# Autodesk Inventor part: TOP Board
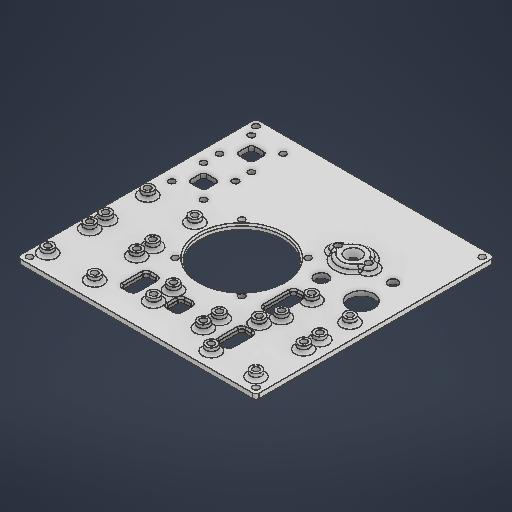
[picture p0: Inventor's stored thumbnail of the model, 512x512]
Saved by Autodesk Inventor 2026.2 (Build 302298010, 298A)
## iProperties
Created: 2026-05
Part Number: TOP Board
Material: 일반
Document SubType Name: Modeling
Designer: work
Density: 1 g/cm^3
Appearance: 기본값
Author: work
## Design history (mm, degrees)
sketch "스케치1"
  geometry: L1 (0, 0)-(150, 0); L2 (150, 0)-(150, -150); L3 (150, -150)-(0, -150); L4 (0, -150)-(0, 0); L5 (146, -4)-(4, -4); L6 (4, -4)-(4, -146); L7 (4, -146)-(146, -146); L8 (146, -146)-(146, -4); L9 (10, -10)-(38, -10); L10 (38, -10)-(38, -40); L11 (38, -40)-(10, -40); L12 (10, -40)-(10, -10); L13 (34, -17)-(42, -17); L14 (42, -17)-(42, -33); L15 (42, -33)-(34, -33); L16 (34, -33)-(34, -17); L17 (34, -17)-(42, -33); L18 (42, -17)-(34, -33); L19 (10, -50)-(34, -50); L20 (34, -50)-(34, -69); L21 (34, -69)-(10, -69); L22 (10, -69)-(10, -50); L23 (10, -50)-(34, -69); L24 (34, -50)-(10, -69); L25 (53, -20)-(53, -30); L26 (38, -25)-(53, -25); L27 (68.5, -17.5)-(49.5, -17.5); L28 (49.5, -17.5)-(49.5, -32.5); L29 (49.5, -32.5)-(68.5, -32.5); L30 (68.5, -32.5)-(68.5, -17.5); L31 (68.5, -17.5)-(49.5, -32.5); L32 (49.5, -17.5)-(68.5, -32.5); L33 (53, -25)-(59, -25); L34 (43, -84)-(18, -84); L35 (18, -104)-(18, -69); L36 (58.14, -49.14)-(99.86, -49.14); L37 (99.86, -49.14)-(99.86, -90.86); L38 (99.86, -90.86)-(58.14, -90.86); L39 (58.14, -90.86)-(58.14, -49.14); L40 (58.14, -49.14)-(99.86, -90.86); L41 (99.86, -49.14)-(58.14, -90.86); L42 (38, -49.5)-(46, -49.5); L43 (46, -49.5)-(46, -69.5); L44 (46, -69.5)-(38, -69.5); L45 (38, -69.5)-(38, -49.5); L46 (38, -49.5)-(46, -69.5); L47 (46, -49.5)-(38, -69.5); L48 (22, -59.5)-(42, -59.5); L49 (69, -20)-(77, -20); L50 (77, -20)-(77, -30); L51 (77, -30)-(69, -30); L52 (69, -30)-(69, -20); L53 (69, -20)-(77, -30); L54 (77, -20)-(69, -30); L55 (59, -25)-(73, -25); L56 (83, -18.75)-(83, -31.25); L57 (94, -17)-(102, -17); L58 (102, -17)-(102, -33); L59 (102, -33)-(94, -33); L60 (94, -33)-(94, -17); L61 (94, -17)-(102, -33); L62 (102, -17)-(94, -33); L63 (83, -25)-(98, -25); L64 (113, -11.8)-(142.5, -11.8)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; C1 r 2 at (146, -4); C2 r 2 at (4, -4); C3 r 2 at (4, -146); C4 r 2 at (146, -146); C5 r 2 at (10, -10); C6 r 2 at (38, -10); C7 r 2 at (38, -40); C8 r 2 at (10, -40); C9 r 2 at (10, -50); C10 r 2 at (34, -50); C11 r 2 at (34, -69); C12 r 2 at (10, -69); C13 r 1.6 at (53, -20); C14 r 1.6 at (53, -30); C15 r 8 at (18, -84); C16 r 4.15 at (43, -84); C17 r 3 at (18, -104); C18 r 26 at (79, -70); C19 r 2 at (99.86, -49.14); C20 r 2 at (58.14, -49.14); C21 r 2 at (58.14, -90.86); C22 r 2 at (99.86, -90.86); C23 r 2 at (83, -18.75); C24 r 2 at (83, -31.25); C25 r 2 at (113, -11.8); C26 r 2 at (113, -38.2); C27 r 2 at (142.5, -38.2); C28 r 2 at (142.5, -11.8); C29 r 2 at (113, -74.6); C30 r 2 at (113, -48.2); C31 r 2 at (142.5, -48.2); C32 r 2 at (142.5, -74.6); C33 r 7.6 at (43, -104); C34 r 2 at (33.4, -104); C35 r 2 at (52.6, -104); C36 r 2 at (43, -104); C37 r 2 at (142.5, -89.6); C38 r 2 at (122.5, -89.6); C39 r 2 at (122.5, -109.6); C40 r 2 at (142.5, -109.6); C41 r 2 at (122.5, -119.6); C42 r 2 at (142.5, -119.6); C43 r 2 at (142.5, -139.6); C44 r 2 at (122.5, -139.6); 3 further points
  constraints: 220 end point, 44 centre point, 37 coincident, 34 parallel, 31 midpoint, 23 perpendicular, 22 horizontal, 6 collinear, 3 point on line, 3 vertical, 2 tangent
  dimensions: "d0" = 150 distance of L2.end L3.end; "d1" = 150 distance of L1.end L2.end; "d2" = 4 diameter of C1; "d3" = 4 diameter of C2; "d4" = 4 diameter of C3; "d5" = 4 diameter of C4; "d6" = 4 distance between parallel lines of L1 L5; "d7" = 4 distance between parallel lines of L4 L6; "d8" = 4 distance between parallel lines of L2 L8; "d9" = 4 distance between parallel lines of L3 L7; "d10" = 28 distance of L10.end L11.end; "d11" = 30 distance of L9.end L10.end; "d12" = 4 diameter of C5; "d13" = 4 diameter of C6; "d14" = 4 diameter of C7; "d15" = 4 diameter of C8; "d16" = 8 distance of L14.end L15.end; "d17" = 16 distance of L13.end L14.end; "d18" = 10 distance between parallel lines of L1 L9; "d19" = 10 distance between parallel lines of L4 L12; "d20" = 24 distance of L20.end L21.end; "d21" = 19 distance of L19.end L20.end; "d22" = 10 distance between parallel lines of L11 L19; "d23" = 4 diameter of C9; "d24" = 4 diameter of C10; "d25" = 4 diameter of C11; "d26" = 4 diameter of C12; "d27" = 10 distance of L25.start L25.end; "d28" = 3.2 diameter of C13; "d29" = 3.2 diameter of C14; "d30" = 15 distance of L26.start L26.end; "d31" = 19 distance of L29.end L28.end; "d32" = 15 distance of L28.end L27.end; "d33" = 6 distance of L26.end L33.end; "d34" = 16 diameter of C15; "d35" = 8 distance from line of L22 L34.end; "d36" = 15 distance from line of L21 L34.end; "d37" = 8.3 diameter of C16; "d38" = 25 distance of L34.start L34.end; "d39" = 6 diameter of C17; "d40" = 20 distance from line of L34 L35.start; "d42" = 52 diameter of C18; "d43" = 59 distance of L36.end L38.end; "d44" = 4 diameter of C19; "d45" = 4 diameter of C20; "d46" = 4 diameter of C21; "d47" = 4 diameter of C22; "d48" = 45 distance from line of L20 C18.centre; "d49" = 70 distance from line of L1 C18.centre; "d50" = 8 distance of L43.end L44.end; "d51" = 20 distance of L42.end L43.end; "d52" = 20 distance of L48.start L48.end; "d53" = 8 distance of L50.end L51.end; "d54" = 10 distance of L49.end L50.end; "d55" = 20 distance of L26.end L55.end; "d56" = 12.5 distance of L56.start L56.end; "d57" = 4 diameter of C23; "d58" = 4 diameter of C24; "d61" = 8 distance of L58.end L59.end; "d62" = 16 distance of L57.end L58.end; "d63" = 15 distance of L63.start L63.end; "d64" = 10 distance of L55.end L63.start; "d65" = 26.4 distance of L64.end L65.end; "d66" = 29.5 distance of L65.end L66.end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
extrude "돌출1" new body sketch "스케치1" distance "d100" = 3; taper "d101" = 0 deg
sketch "스케치2"
  geometry: L1 (0, 150)-(-150, 150) reference; L2 (-150, 150)-(-150, 0) reference; L3 (-150, 0)-(0, 0) reference; L4 (0, 0)-(0, 150) reference; L5 (-94, 17)-(-102, 17) reference; L6 (-102, 17)-(-102, 33) reference; L7 (-102, 33)-(-94, 33) reference; L8 (-94, 33)-(-94, 17) reference; L9 (-69, 20)-(-77, 20) reference; L10 (-77, 20)-(-77, 30) reference; L11 (-77, 30)-(-69, 30) reference; L12 (-69, 30)-(-69, 20) reference; L13 (-38, 49.5)-(-46, 49.5) reference; L14 (-46, 49.5)-(-46, 69.5) reference; L15 (-46, 69.5)-(-38, 69.5) reference; L16 (-38, 69.5)-(-38, 49.5) reference; L17 (-34, 17)-(-42, 17) reference; L18 (-42, 17)-(-42, 33) reference; L19 (-42, 33)-(-34, 33) reference; L20 (-34, 33)-(-34, 17) reference; C1 r 2 at (-122.5, 139.6) reference; C2 r 2 at (-142.5, 119.6) reference; C3 r 2 at (-142.5, 109.6) reference; C4 r 2 at (-122.5, 89.6) reference; C5 r 2 at (-43, 104) reference; C6 r 2 at (-33.4, 104) reference; C7 r 2 at (-142.5, 48.2) reference; C8 r 2 at (-113, 74.6) reference; C9 r 2 at (-142.5, 38.2) reference; C10 r 2 at (-113, 11.8) reference; C11 r 2 at (-83, 18.75) reference; C12 r 4.15 at (-43, 84) reference; C13 r 1.6 at (-53, 30) reference; C14 r 2 at (-10, 69) reference; C15 r 2 at (-34, 50) reference; C16 r 2 at (-10, 40) reference; C17 r 2 at (-38, 40) reference; C18 r 2 at (-38, 10) reference; C19 r 2 at (-10, 10) reference; C20 r 2 at (-146, 146) reference; C21 r 2 at (-4, 146) reference; C22 r 2 at (-4, 4) reference; C23 r 2 at (-146, 4) reference; C24 r 2 at (-10, 50) reference; C25 r 2 at (-34, 69) reference; C26 r 1.6 at (-53, 20) reference; C27 r 8 at (-18, 84) reference; C28 r 3 at (-18, 104) reference; C29 r 2 at (-83, 31.25) reference; C30 r 2 at (-113, 38.2) reference; C31 r 2 at (-142.5, 11.8) reference; C32 r 2 at (-113, 48.2) reference; C33 r 2 at (-142.5, 74.6) reference; C34 r 2 at (-52.6, 104) reference; C35 r 2 at (-142.5, 89.6) reference; C36 r 2 at (-122.5, 109.6) reference; C37 r 2 at (-122.5, 119.6) reference; C38 r 2 at (-142.5, 139.6) reference; C39 r 2 at (-99.86, 90.86) reference; C40 r 2 at (-58.14, 90.86) reference; C41 r 2 at (-58.14, 49.14) reference; C42 r 2 at (-99.86, 49.14) reference; C43 r 26 at (-79, 70) reference; C44 r 3.5 at (-10, 10); 1 further point
  constraints: 1 centre point, 1 coincident
  dimensions: "d102" = 7 diameter of C44
extrude "돌출2" join sketch "스케치2" distance "d103" = 4; taper "d104" = 0 deg
fillet "모깎기1" dims "d105" = 2
sketch "스케치4"
  geometry: L1 (-38, 65.225)-(-38, 53.775) reference; L2 (-39.477, 49.5)-(-46, 49.5) reference; L3 (-46, 49.5)-(-46, 69.5) reference; L4 (-46, 69.5)-(-39.477, 69.5) reference; L5 (-34, 17)-(-42, 17) reference; L6 (-42, 17)-(-42, 33) reference; L7 (-42, 33)-(-34, 33) reference; L8 (-34, 33)-(-34, 17) reference; L9 (-69, 20)-(-77, 20) reference; L10 (-77, 20)-(-77, 30) reference; L11 (-77, 30)-(-69, 30) reference; L12 (-69, 30)-(-69, 20) reference; L13 (-94, 17)-(-102, 17) reference; L14 (-102, 17)-(-102, 33) reference; L15 (-102, 33)-(-94, 33) reference; L16 (-94, 33)-(-94, 17) reference; L17 (0, 150)-(-150, 150) reference; L18 (-150, 150)-(-150, 0) reference; L19 (-150, 0)-(0, 0) reference; L20 (0, 0)-(0, 150) reference; C1 r 5.5 at (-113, 74.6) reference; C2 r 5.5 at (-142.5, 11.8) reference; C3 r 5.5 at (-83, 31.25) reference; C4 r 5.5 at (-10, 69) reference; C5 r 5.5 at (-38, 10) reference; C6 r 26 at (-79, 70) reference; C7 r 2 at (-99.86, 49.14) reference; C8 r 2 at (-58.14, 49.14) reference; C9 r 2 at (-58.14, 90.86) reference; C10 r 2 at (-99.86, 90.86) reference; C11 r 2 at (-142.5, 139.6) reference; C12 r 2 at (-122.5, 119.6) reference; C13 r 2 at (-122.5, 109.6) reference; C14 r 2 at (-142.5, 89.6) reference; C15 r 2 at (-52.6, 104) reference; C16 r 3 at (-18, 104) reference; C17 r 8 at (-18, 84) reference; C18 r 2 at (-146, 4) reference; C19 r 2 at (-4, 4) reference; C20 r 2 at (-4, 146) reference; C21 r 2 at (-146, 146) reference; C22 r 4.15 at (-43, 84) reference; C23 r 2 at (-33.4, 104) reference; C24 r 2 at (-43, 104) reference; C25 r 2 at (-122.5, 89.6) reference; C26 r 2 at (-142.5, 109.6) reference; C27 r 2 at (-142.5, 119.6) reference; C28 r 2 at (-122.5, 139.6) reference; C29 r 5.5 at (-10, 10) reference; C30 r 5.5 at (-83, 18.75) reference; C31 r 5.5 at (-113, 11.8) reference; C32 r 5.5 at (-142.5, 74.6) reference; A1 r 5.5 centre (-142.5, 48.2) between (-140.209, 43.2) and (-144.791, 43.2) reference; A2 r 5.5 centre (-142.5, 38.2) between (-144.791, 43.2) and (-140.209, 43.2) reference; A3 r 5.5 centre (-113, 48.2) between (-110.709, 43.2) and (-115.291, 43.2) reference; A4 r 5.5 centre (-113, 38.2) between (-115.291, 43.2) and (-110.709, 43.2) reference; A5 r 5.5 centre (-34, 69) between (-38, 65.225) and (-39.477, 69.5) reference; A6 r 5.5 centre (-34, 50) between (-34.962, 44.585) and (-38, 53.775) reference; A7 r 5.5 centre (-38, 40) between (-37.038, 45.415) and (-34.962, 44.585) reference; A8 r 5.5 centre (-34, 50) between (-39.477, 49.5) and (-37.038, 45.415) reference; A9 r 5.5 centre (-10, 50) between (-7.709, 45) and (-12.291, 45) reference; A10 r 5.5 centre (-10, 40) between (-12.291, 45) and (-7.709, 45) reference; A11 r 5.5 centre (-53, 30) between (-50.709, 25) and (-55.291, 25) reference; A12 r 5.5 centre (-53, 20) between (-55.291, 25) and (-50.709, 25) reference; 1 further point
  node "투영된 루프3"
fillet "모깎기2" dims "d110" = 2
chamfer "모따기1" distance "d111" = 1; stored, may be unused: second distance "d112" = 2, angle "d113" = 45 deg
sketch "스케치5"
  geometry: L1 (-2, -150)-(-148, -150) reference; L2 (0, -2)-(0, -148) reference; L3 (-148, 0)-(-2, 0) reference; L4 (-150, -148)-(-150, -2) reference; L5 (-127.5, -132.6)-(-127.5, -126.6) reference; L6 (-135.5, -134.6)-(-129.5, -134.6) reference; L7 (-137.5, -126.6)-(-137.5, -132.6) reference; L8 (-129.5, -124.6)-(-135.5, -124.6) reference; L9 (-127.5, -102.6)-(-127.5, -96.6) reference; L10 (-135.5, -104.6)-(-129.5, -104.6) reference; L11 (-137.5, -96.6)-(-137.5, -102.6) reference; L12 (-129.5, -94.6)-(-135.5, -94.6) reference; L13 (-94, -31)-(-94, -19) reference; L14 (-100, -33)-(-96, -33) reference; L15 (-102, -19)-(-102, -31) reference; L16 (-96, -17)-(-100, -17) reference; L17 (-69, -28)-(-69, -22) reference; L18 (-75, -30)-(-71, -30) reference; L19 (-77, -22)-(-77, -28) reference; L20 (-71, -20)-(-75, -20) reference; L21 (-38, -67.5)-(-38, -51.5) reference; L22 (-44, -69.5)-(-40, -69.5) reference; L23 (-46, -51.5)-(-46, -67.5) reference; L24 (-40, -49.5)-(-44, -49.5) reference; L25 (-34, -31)-(-34, -19) reference; L26 (-40, -33)-(-36, -33) reference; L27 (-42, -19)-(-42, -31) reference; L28 (-36, -17)-(-40, -17) reference; C1 r 2 at (-122.5, -139.6) reference; C2 r 2 at (-142.5, -119.6) reference; C3 r 2 at (-142.5, -109.6) reference; C4 r 2 at (-122.5, -89.6) reference; C5 r 2 at (-43, -104) reference; C6 r 2 at (-33.4, -104) reference; C7 r 2 at (-142.5, -48.2) reference; C8 r 2 at (-113, -74.6) reference; C9 r 2 at (-142.5, -38.2) reference; C10 r 2 at (-113, -11.8) reference; C11 r 2 at (-83, -18.75) reference; C12 r 4.15 at (-43, -84) reference; C13 r 1.6 at (-53, -30) reference; C14 r 2 at (-10, -69) reference; C15 r 2 at (-34, -50) reference; C16 r 2 at (-10, -40) reference; C17 r 2 at (-38, -40) reference; C18 r 2 at (-38, -10) reference; C19 r 2 at (-10, -10) reference; C20 r 2 at (-146, -146) reference; C21 r 2 at (-4, -146) reference; C22 r 2 at (-4, -4) reference; C23 r 2 at (-146, -4) reference; C24 r 2 at (-10, -50) reference; C25 r 2 at (-34, -69) reference; C26 r 1.6 at (-53, -20) reference; C27 r 8 at (-18, -84) reference; C28 r 3 at (-18, -104) reference; C29 r 2 at (-83, -31.25) reference; C30 r 2 at (-113, -38.2) reference; C31 r 2 at (-142.5, -11.8) reference; C32 r 2 at (-113, -48.2) reference; C33 r 2 at (-142.5, -74.6) reference; C34 r 2 at (-52.6, -104) reference; C35 r 2 at (-142.5, -89.6) reference; C36 r 2 at (-122.5, -109.6) reference; C37 r 2 at (-122.5, -119.6) reference; C38 r 2 at (-142.5, -139.6) reference; C39 r 2 at (-99.86, -90.86) reference; C40 r 2 at (-58.14, -90.86) reference; C41 r 2 at (-58.14, -49.14) reference; C42 r 2 at (-99.86, -49.14) reference; C43 r 26 at (-79, -70) reference; C44 r 7.6 at (-43, -104); A1 r 2 centre (-148, -148) between (-150, -148) and (-148, -150) reference; A2 r 2 centre (-2, -148) between (-2, -150) and (0, -148) reference; A3 r 2 centre (-2, -2) between (0, -2) and (-2, 0) reference; A4 r 2 centre (-148, -2) between (-148, 0) and (-150, -2) reference; A5 r 2 centre (-129.5, -126.6) between (-127.5, -126.6) and (-129.5, -124.6) reference; A6 r 2 centre (-129.5, -132.6) between (-129.5, -134.6) and (-127.5, -132.6) reference; A7 r 2 centre (-135.5, -132.6) between (-137.5, -132.6) and (-135.5, -134.6) reference; A8 r 2 centre (-135.5, -126.6) between (-135.5, -124.6) and (-137.5, -126.6) reference; A9 r 2 centre (-129.5, -96.6) between (-127.5, -96.6) and (-129.5, -94.6) reference; A10 r 2 centre (-129.5, -102.6) between (-129.5, -104.6) and (-127.5, -102.6) reference; A11 r 2 centre (-135.5, -102.6) between (-137.5, -102.6) and (-135.5, -104.6) reference; A12 r 2 centre (-135.5, -96.6) between (-135.5, -94.6) and (-137.5, -96.6) reference; A13 r 2 centre (-96, -19) between (-94, -19) and (-96, -17) reference; A14 r 2 centre (-96, -31) between (-96, -33) and (-94, -31) reference; A15 r 2 centre (-100, -31) between (-102, -31) and (-100, -33) reference; A16 r 2 centre (-100, -19) between (-100, -17) and (-102, -19) reference; A17 r 2 centre (-71, -22) between (-69, -22) and (-71, -20) reference; A18 r 2 centre (-71, -28) between (-71, -30) and (-69, -28) reference; A19 r 2 centre (-75, -28) between (-77, -28) and (-75, -30) reference; A20 r 2 centre (-75, -22) between (-75, -20) and (-77, -22) reference; A21 r 2 centre (-40, -51.5) between (-38, -51.5) and (-40, -49.5) reference; A22 r 2 centre (-40, -67.5) between (-40, -69.5) and (-38, -67.5) reference; A23 r 2 centre (-44, -67.5) between (-46, -67.5) and (-44, -69.5) reference; A24 r 2 centre (-44, -51.5) between (-44, -49.5) and (-46, -51.5) reference; A25 r 2 centre (-36, -19) between (-34, -19) and (-36, -17) reference; A26 r 2 centre (-36, -31) between (-36, -33) and (-34, -31) reference; A27 r 2 centre (-40, -31) between (-42, -31) and (-40, -33) reference; A28 r 2 centre (-40, -19) between (-40, -17) and (-42, -19) reference; 1 further point
  constraints: 1 centre point, 1 coincident, 1 tangent
  node "투영된 루프4"
sketch "스케치6"
  geometry: L1 (-78, 28)-(-78, 22) reference; L2 (-71, 31)-(-75, 31) reference; L3 (-68, 22)-(-68, 28) reference; L4 (-75, 19)-(-71, 19) reference; L5 (-129.5, 94.6)-(-135.5, 94.6) reference; L6 (-137.5, 96.6)-(-137.5, 102.6) reference; L7 (-135.5, 104.6)-(-129.5, 104.6) reference; L8 (-127.5, 102.6)-(-127.5, 96.6) reference; L9 (-129.5, 124.6)-(-135.5, 124.6) reference; L10 (-137.5, 126.6)-(-137.5, 132.6) reference; L11 (-135.5, 134.6)-(-129.5, 134.6) reference; L12 (-127.5, 132.6)-(-127.5, 126.6) reference; L13 (-150, 148)-(-150, 2) reference; L14 (-148, 0)-(-2, 0) reference; L15 (0, 2)-(0, 148) reference; L16 (-2, 150)-(-148, 150) reference; L17 (-37, 54.61)-(-37, 64.39) reference; L18 (-44, 48.5)-(-40, 48.5) reference; L19 (-47, 67.5)-(-47, 51.5) reference; L20 (-40, 70.5)-(-44, 70.5) reference; L21 (-43, 31)-(-43, 19) reference; L22 (-36, 34)-(-40, 34) reference; L23 (-33, 19)-(-33, 31) reference; L24 (-40, 16)-(-36, 16) reference; L25 (-103, 31)-(-103, 19) reference; L26 (-96, 34)-(-100, 34) reference; L27 (-93, 19)-(-93, 31) reference; L28 (-100, 16)-(-96, 16) reference; C1 r 27 at (-79, 70) reference; C2 r 5.5 at (-113, 74.6) reference; C3 r 5.5 at (-142.5, 11.8) reference; C4 r 5.5 at (-83, 31.25) reference; C5 r 5.5 at (-10, 69) reference; C6 r 5.5 at (-38, 10) reference; C7 r 2 at (-99.86, 49.14) reference; C8 r 2 at (-58.14, 49.14) reference; C9 r 2 at (-58.14, 90.86) reference; C10 r 2 at (-99.86, 90.86) reference; C11 r 2 at (-142.5, 139.6) reference; C12 r 2 at (-122.5, 119.6) reference; C13 r 2 at (-122.5, 109.6) reference; C14 r 2 at (-142.5, 89.6) reference; C15 r 2 at (-52.6, 104) reference; C16 r 3 at (-18, 104) reference; C17 r 8 at (-18, 84) reference; C18 r 2 at (-146, 4) reference; C19 r 2 at (-4, 4) reference; C20 r 2 at (-4, 146) reference; C21 r 2 at (-146, 146) reference; C22 r 4.15 at (-43, 84) reference; C23 r 2 at (-33.4, 104) reference; C24 r 2 at (-43, 104) reference; C25 r 2 at (-122.5, 89.6) reference; C26 r 2 at (-142.5, 109.6) reference; C27 r 2 at (-142.5, 119.6) reference; C28 r 2 at (-122.5, 139.6) reference; C29 r 5.5 at (-10, 10) reference; C30 r 5.5 at (-83, 18.75) reference; C31 r 5.5 at (-113, 11.8) reference; C32 r 5.5 at (-142.5, 74.6) reference; C33 r 4 at (-52.6, 104); C34 r 4 at (-33.4, 104); A1 r 3 centre (-75, 28) between (-75, 31) and (-78, 28) reference; A2 r 3 centre (-71, 28) between (-68, 28) and (-71, 31) reference; A3 r 3 centre (-71, 22) between (-71, 19) and (-68, 22) reference; A4 r 3 centre (-75, 22) between (-78, 22) and (-75, 19) reference; A5 r 5.5 centre (-142.5, 48.2) between (-140.209, 43.2) and (-144.791, 43.2) reference; A6 r 5.5 centre (-142.5, 38.2) between (-144.791, 43.2) and (-140.209, 43.2) reference; A7 r 5.5 centre (-113, 48.2) between (-110.709, 43.2) and (-115.291, 43.2) reference; A8 r 5.5 centre (-113, 38.2) between (-115.291, 43.2) and (-110.709, 43.2) reference; A9 r 5.5 centre (-10, 50) between (-7.709, 45) and (-12.291, 45) reference; A10 r 5.5 centre (-10, 40) between (-12.291, 45) and (-7.709, 45) reference; A11 r 2 centre (-135.5, 96.6) between (-137.5, 96.6) and (-135.5, 94.6) reference; A12 r 2 centre (-135.5, 102.6) between (-135.5, 104.6) and (-137.5, 102.6) reference; A13 r 2 centre (-129.5, 102.6) between (-127.5, 102.6) and (-129.5, 104.6) reference; A14 r 2 centre (-129.5, 96.6) between (-129.5, 94.6) and (-127.5, 96.6) reference; A15 r 2 centre (-135.5, 126.6) between (-137.5, 126.6) and (-135.5, 124.6) reference; A16 r 2 centre (-135.5, 132.6) between (-135.5, 134.6) and (-137.5, 132.6) reference; A17 r 2 centre (-129.5, 132.6) between (-127.5, 132.6) and (-129.5, 134.6) reference; A18 r 2 centre (-129.5, 126.6) between (-129.5, 124.6) and (-127.5, 126.6) reference; A19 r 2 centre (-148, 148) between (-148, 150) and (-150, 148) reference; A20 r 2 centre (-148, 2) between (-150, 2) and (-148, 0) reference; A21 r 2 centre (-2, 2) between (-2, 0) and (0, 2) reference; A22 r 2 centre (-2, 148) between (0, 148) and (-2, 150) reference; A23 r 5.5 centre (-53, 30) between (-50.709, 25) and (-55.291, 25) reference; A24 r 5.5 centre (-53, 20) between (-55.291, 25) and (-50.709, 25) reference; A25 r 3 centre (-40, 67.5) between (-39.313, 70.42) and (-40, 70.5) reference; A26 r 5.5 centre (-34, 69) between (-37, 64.39) and (-39.313, 70.42) reference; A27 r 5.5 centre (-34, 50) between (-34.962, 44.585) and (-37, 54.61) reference; A28 r 5.5 centre (-38, 40) between (-37.038, 45.415) and (-34.962, 44.585) reference; A29 r 5.5 centre (-34, 50) between (-39.313, 48.58) and (-37.038, 45.415) reference; A30 r 3 centre (-40, 51.5) between (-40, 48.5) and (-39.313, 48.58) reference; A31 r 3 centre (-44, 51.5) between (-47, 51.5) and (-44, 48.5) reference; A32 r 3 centre (-44, 67.5) between (-44, 70.5) and (-47, 67.5) reference; A33 r 3 centre (-40, 31) between (-40, 34) and (-43, 31) reference; A34 r 3 centre (-36, 31) between (-33, 31) and (-36, 34) reference; A35 r 3 centre (-36, 19) between (-36, 16) and (-33, 19) reference; A36 r 3 centre (-40, 19) between (-43, 19) and (-40, 16) reference; A37 r 3 centre (-100, 31) between (-100, 34) and (-103, 31) reference; A38 r 3 centre (-96, 31) between (-93, 31) and (-96, 34) reference; A39 r 3 centre (-96, 19) between (-96, 16) and (-93, 19) reference; A40 r 3 centre (-100, 19) between (-103, 19) and (-100, 16) reference; 6 further points
  constraints: 3 coincident, 2 centre point, 3 other
  dimensions: "d114" = 8 diameter of C33; "d115" = 8 diameter of C34
extrude "돌출3" join sketch "스케치6" distance "d116" = 3; taper "d117" = 0 deg
fillet "모깎기3" dims "d118" = 2
fillet "모깎기4" dims "d119" = 2
extrude "돌출4" cut sketch "스케치5" distance "d120" = 3; taper "d121" = 0 deg
chamfer "모따기2" distance "d122" = 3; stored, may be unused: second distance "d123" = 2, angle "d124" = 45 deg
node "솔리드1"
feature "스케치 연계 패턴1"
node "투영된 루프1"
sketch "스케치3"
  geometry: L1 (-34, 17)-(-42, 17) reference; L2 (-42, 17)-(-42, 33) reference; L3 (-42, 33)-(-34, 33) reference; L4 (-34, 33)-(-34, 17) reference; L5 (-38, 49.5)-(-46, 49.5) reference; L6 (-46, 49.5)-(-46, 69.5) reference; L7 (-46, 69.5)-(-38, 69.5) reference; L8 (-38, 69.5)-(-38, 49.5) reference; L9 (-69, 20)-(-77, 20) reference; L10 (-77, 20)-(-77, 30) reference; L11 (-77, 30)-(-69, 30) reference; L12 (-69, 30)-(-69, 20) reference; L13 (-94, 17)-(-102, 17) reference; L14 (-102, 17)-(-102, 33) reference; L15 (-102, 33)-(-94, 33) reference; L16 (-94, 33)-(-94, 17) reference; L17 (0, 150)-(-150, 150) reference; L18 (-150, 150)-(-150, 0) reference; L19 (-150, 0)-(0, 0) reference; L20 (0, 0)-(0, 150) reference; C1 r 26 at (-79, 70) reference; C2 r 2 at (-99.86, 49.14) reference; C3 r 2 at (-58.14, 49.14) reference; C4 r 2 at (-58.14, 90.86) reference; C5 r 2 at (-99.86, 90.86) reference; C6 r 2 at (-142.5, 139.6) reference; C7 r 2 at (-122.5, 119.6) reference; C8 r 2 at (-122.5, 109.6) reference; C9 r 2 at (-142.5, 89.6) reference; C10 r 2 at (-52.6, 104) reference; C11 r 2 at (-142.5, 74.6) reference; C12 r 2 at (-113, 48.2) reference; C13 r 2 at (-142.5, 11.8) reference; C14 r 2 at (-113, 38.2) reference; C15 r 2 at (-83, 31.25) reference; C16 r 3 at (-18, 104) reference; C17 r 8 at (-18, 84) reference; C18 r 1.6 at (-53, 20) reference; C19 r 2 at (-34, 69) reference; C20 r 2 at (-10, 50) reference; C21 r 2 at (-146, 4) reference; C22 r 2 at (-4, 4) reference; C23 r 2 at (-4, 146) reference; C24 r 2 at (-146, 146) reference; C25 r 2 at (-38, 10) reference; C26 r 2 at (-38, 40) reference; C27 r 2 at (-10, 40) reference; C28 r 2 at (-34, 50) reference; C29 r 2 at (-10, 69) reference; C30 r 1.6 at (-53, 30) reference; C31 r 4.15 at (-43, 84) reference; C32 r 2 at (-83, 18.75) reference; C33 r 2 at (-113, 11.8) reference; C34 r 2 at (-142.5, 38.2) reference; C35 r 2 at (-113, 74.6) reference; C36 r 2 at (-142.5, 48.2) reference; C37 r 2 at (-33.4, 104) reference; C38 r 2 at (-43, 104) reference; C39 r 2 at (-122.5, 89.6) reference; C40 r 2 at (-142.5, 109.6) reference; C41 r 2 at (-142.5, 119.6) reference; C42 r 2 at (-122.5, 139.6) reference; C43 r 5.5 at (-10, 10) reference; 20 further points
  constraints: 19 coincident
node "투영된 루프2"
node "투영된 루프5"
